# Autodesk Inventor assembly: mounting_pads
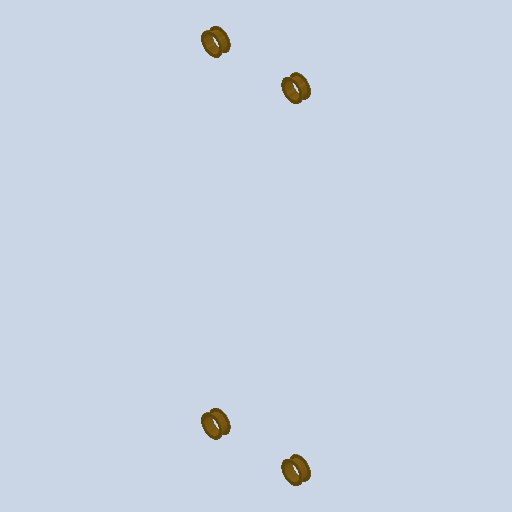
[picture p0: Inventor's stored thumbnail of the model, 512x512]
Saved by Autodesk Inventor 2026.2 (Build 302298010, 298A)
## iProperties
Created: 2026-10
Part Number: mounting_pads
Document SubType Name: Assembly
Designer: mel
Author: mel
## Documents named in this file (2)
- D:\travail\année 2026-2027\1 sti2d IT\poubelle à verre\raspberry-pico-2-microcontroller-rp2350-1.snapshot.5\raspberry_pico_2\raspberry_pico_2\mounting_pads.iam
- D:\travail\année 2026-2027\1 sti2d IT\poubelle à verre\raspberry-pico-2-microcontroller-rp2350-1.snapshot.5\raspberry_pico_2\raspberry_pico_2\mounting_pad.ipt
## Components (4 placed, 4 different names)
1. 2625
2. 2626
3. 2627
4. 2628
